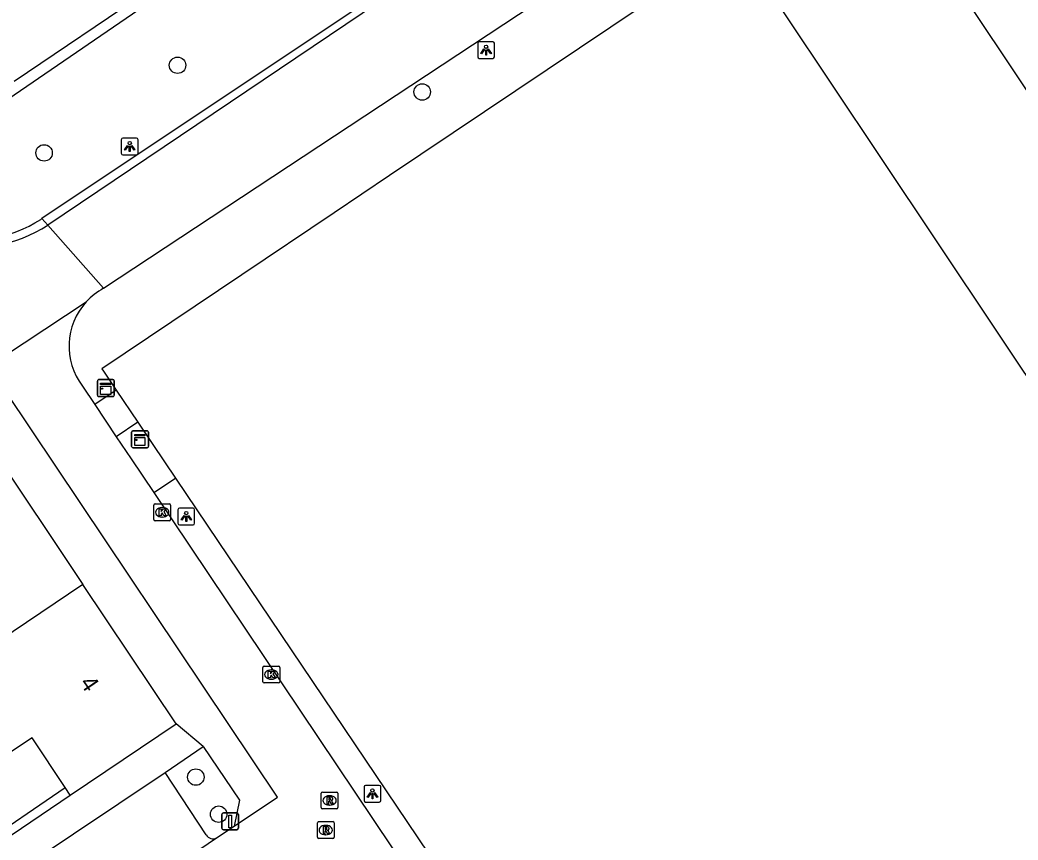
# Model space of a CAD drawing. Extents: x 158797 to 159887, y 384318 to 385255.
# Drawn here: x 159000.1 to 159059.5, y 384461 to 384509.8 of the extents above; entities that cross this region are included whole.
import ezdxf

# ---------------------------------------------------------------- set-up
doc = ezdxf.new("R2010")
doc.units = 0
for name, color, linetype in [('IMGEO_Boom', 7, 'Continuous'), ('IMGEO_Haag', 7, 'Continuous'), ('IMGEO_Kast', 7, 'Continuous'), ('IMGEO_Kolk', 7, 'Continuous'), ('IMGEO_Lichtpunt', 7, 'Continuous'), ('IMGEO_Pand', 7, 'Continuous'), ('IMGEO_Pand_nummerreeks', 7, 'Continuous'), ('IMGEO_Parkeervlak_open', 7, 'Continuous'), ('IMGEO_Rijbaan_lokaal_open', 7, 'Continuous'), ('IMGEO_Rioolput', 7, 'Continuous'), ('IMGEO_Verkeersbordpaal', 7, 'Continuous'), ('IMGEO_Voetpad_open', 7, 'Continuous')]:
    doc.layers.add(name, color=color, linetype=linetype)

msp = doc.modelspace()

# ---------------------------------------------------------------- linework, layer by layer
at = {"layer": 'IMGEO_Boom'}
for centre in [(159009.519, 384507.08), (159024.082, 384505.491), (159001.577, 384501.867), (159010.609, 384464.735), (159011.967, 384462.527)]:
    msp.add_circle(centre, 0.489, dxfattribs=at)
at = {"layer": 'IMGEO_Haag'}
for points in [[(158980.903, 384520.981), (158980.583, 384520.752), (158993.483, 384501.012), (159020.48, 384519.493)], [(159007.798, 384511.537), (158999.786, 384506.109)], [(158997.867, 384460.106), (158997.595, 384460.538), (159002.823, 384464.117)]]:
    msp.add_lwpolyline(points, dxfattribs=at)
at = {"layer": 'IMGEO_Kast'}
for p, q in [((159004.747, 384487.453), (159004.747, 384488.294)), ((159004.747, 384488.294), (159004.747, 384487.453)), ((159004.822, 384488.378), (159005.663, 384488.378)), ((159005.663, 384488.378), (159004.822, 384488.378)), ((159005.747, 384488.303), (159005.747, 384487.462)), ((159005.747, 384487.462), (159005.747, 384488.303)), ((159005.672, 384487.378), (159004.831, 384487.378)), ((159004.831, 384487.378), (159005.672, 384487.378)), ((159006.786, 384484.406), (159006.786, 384485.247)), ((159006.786, 384485.247), (159006.786, 384484.406)), ((159006.861, 384485.331), (159007.702, 384485.331)), ((159007.702, 384485.331), (159006.861, 384485.331)), ((159007.786, 384485.256), (159007.786, 384484.415)), ((159007.786, 384484.415), (159007.786, 384485.256)), ((159007.711, 384484.331), (159006.87, 384484.331)), ((159006.87, 384484.331), (159007.711, 384484.331))]:
    msp.add_line(p, q, dxfattribs=at)
for points in [[(159004.942, 384488.168), (159005.542, 384488.168), (159005.542, 384488.083), (159004.942, 384488.083), (159004.942, 384488.168)], [(159004.942, 384487.993), (159005.542, 384487.993), (159005.542, 384487.504), (159004.942, 384487.504), (159004.942, 384487.993)], [(159006.981, 384485.121), (159007.581, 384485.121), (159007.581, 384485.036), (159006.981, 384485.036), (159006.981, 384485.121)], [(159006.981, 384484.946), (159007.581, 384484.946), (159007.581, 384484.457), (159006.981, 384484.457), (159006.981, 384484.946)]]:
    msp.add_lwpolyline(points, dxfattribs=at)
for centre in [(159005.026, 384487.842), (159007.065, 384484.795)]:
    msp.add_circle(centre, 0.0377, dxfattribs=at)
for centre, start, end in [((159004.825, 384488.3), 92.4484, 184.28452), ((159004.825, 384488.3), 92.4484, 184.28452), ((159005.669, 384488.3), 2.4484, 94.28452), ((159005.669, 384488.3), 2.4484, 94.28452), ((159004.825, 384487.456), 182.4484, 274.28452), ((159004.825, 384487.456), 182.4484, 274.28452), ((159005.669, 384487.456), 272.4484, 4.28452), ((159005.669, 384487.456), 272.4484, 4.28452), ((159006.864, 384485.253), 92.4484, 184.28452), ((159006.864, 384485.253), 92.4484, 184.28452), ((159007.708, 384485.253), 2.4484, 94.28452), ((159007.708, 384485.253), 2.4484, 94.28452), ((159006.864, 384484.409), 182.4484, 274.28452), ((159006.864, 384484.409), 182.4484, 274.28452), ((159007.708, 384484.409), 272.4484, 4.28452), ((159007.708, 384484.409), 272.4484, 4.28452)]:
    msp.add_arc(centre, 0.0779, start, end, dxfattribs=at)
at = {"layer": 'IMGEO_Kolk'}
for p, q in [((159008.105, 384480.061), (159008.105, 384480.913)), ((159008.18, 384480.987), (159009.032, 384480.987)), ((159008.593, 384480.767), (159008.618, 384480.767)), ((159009.106, 384480.913), (159009.106, 384480.061)), ((159008.616, 384480.207), (159008.591, 384480.207)), ((159009.032, 384479.987), (159008.18, 384479.987)), ((159014.599, 384470.409), (159014.599, 384471.261)), ((159014.674, 384471.335), (159015.526, 384471.335)), ((159015.6, 384471.261), (159015.6, 384470.409)), ((159015.087, 384471.115), (159015.112, 384471.115)), ((159015.526, 384470.335), (159014.674, 384470.335)), ((159015.11, 384470.555), (159015.085, 384470.555))]:
    msp.add_line(p, q, dxfattribs=at)
for points in [[(159008.105, 384480.061), (159008.105, 384480.913)], [(159008.18, 384480.987), (159009.032, 384480.987)], [(159008.426, 384480.687), (159008.549, 384480.687), (159008.549, 384480.536), (159008.679, 384480.687), (159008.843, 384480.687), (159008.697, 384480.536), (159008.85, 384480.287), (159008.698, 384480.287), (159008.613, 384480.451), (159008.549, 384480.384), (159008.549, 384480.287), (159008.426, 384480.287), (159008.426, 384480.687)], [(159009.106, 384480.913), (159009.106, 384480.061)], [(159009.032, 384479.987), (159008.18, 384479.987)], [(159014.599, 384470.409), (159014.599, 384471.261)], [(159014.674, 384471.335), (159015.526, 384471.335)], [(159015.6, 384471.261), (159015.6, 384470.409)], [(159014.92, 384471.035), (159015.043, 384471.035), (159015.043, 384470.884), (159015.173, 384471.035), (159015.337, 384471.035), (159015.191, 384470.884), (159015.344, 384470.635), (159015.192, 384470.635), (159015.107, 384470.799), (159015.043, 384470.732), (159015.043, 384470.635), (159014.92, 384470.635), (159014.92, 384471.035)], [(159015.526, 384470.335), (159014.674, 384470.335)]]:
    msp.add_lwpolyline(points, dxfattribs=at)
for centre, start, end in [((159008.182, 384480.911), 91.55205, 178.44795), ((159008.182, 384480.911), 91.55205, 178.44795), ((159009.03, 384480.911), 1.55205, 88.44795), ((159009.03, 384480.911), 1.55205, 88.44795), ((159008.182, 384480.063), 181.55205, 268.44795), ((159008.182, 384480.063), 181.55205, 268.44795), ((159009.03, 384480.063), 271.55205, 358.44795), ((159009.03, 384480.063), 271.55205, 358.44795), ((159014.676, 384471.259), 91.55205, 178.44795), ((159014.676, 384471.259), 91.55205, 178.44795), ((159015.524, 384471.259), 1.55205, 88.44795), ((159015.524, 384471.259), 1.55205, 88.44795), ((159014.676, 384470.411), 181.55205, 268.44795), ((159014.676, 384470.411), 181.55205, 268.44795), ((159015.524, 384470.411), 271.55205, 358.44795), ((159015.524, 384470.411), 271.55205, 358.44795)]:
    msp.add_arc(centre, 0.0765, start, end, dxfattribs=at)
for centre, major_axis, ratio, start_param, end_param in [((159008.592, 384480.487), (-0.387, 0.002), 0.722429, 4.712389, 7.853982), ((159008.617, 384480.487), (-0.39, 0.002), 0.717154, 1.570796, 4.712389), ((159015.086, 384470.835), (-0.387, 0.002), 0.722429, 4.712389, 7.853982), ((159015.111, 384470.835), (-0.39, 0.002), 0.717154, 1.570796, 4.712389)]:
    msp.add_ellipse(centre, major_axis=major_axis, ratio=ratio, start_param=start_param, end_param=end_param, dxfattribs=at)
at = {"layer": 'IMGEO_Lichtpunt'}
for p, q in [((159027.385, 384508.388), (159027.385, 384507.581)), ((159027.385, 384508.388), (159027.385, 384507.581)), ((159028.287, 384508.483), (159027.479, 384508.483)), ((159028.287, 384508.483), (159027.479, 384508.483)), ((159028.381, 384507.581), (159028.381, 384508.388)), ((159028.381, 384507.581), (159028.381, 384508.388)), ((159027.479, 384507.487), (159028.287, 384507.487)), ((159027.479, 384507.487), (159028.287, 384507.487)), ((159006.173, 384502.649), (159006.173, 384501.842)), ((159006.173, 384502.649), (159006.173, 384501.842)), ((159007.075, 384502.744), (159006.267, 384502.744)), ((159007.075, 384502.744), (159006.267, 384502.744)), ((159007.169, 384501.842), (159007.169, 384502.649)), ((159007.169, 384501.842), (159007.169, 384502.649)), ((159006.267, 384501.748), (159007.075, 384501.748)), ((159006.267, 384501.748), (159007.075, 384501.748)), ((159010.443, 384480.734), (159009.635, 384480.734)), ((159010.443, 384480.734), (159009.635, 384480.734)), ((159009.541, 384480.639), (159009.541, 384479.832)), ((159009.541, 384480.639), (159009.541, 384479.832)), ((159010.537, 384479.832), (159010.537, 384480.639)), ((159010.537, 384479.832), (159010.537, 384480.639)), ((159009.635, 384479.738), (159010.443, 384479.738)), ((159009.635, 384479.738), (159010.443, 384479.738)), ((159020.621, 384464.148), (159020.621, 384463.341)), ((159020.621, 384464.148), (159020.621, 384463.341)), ((159021.523, 384464.243), (159020.715, 384464.243)), ((159021.523, 384464.243), (159020.715, 384464.243)), ((159021.617, 384463.341), (159021.617, 384464.148)), ((159021.617, 384463.341), (159021.617, 384464.148)), ((159020.715, 384463.247), (159021.523, 384463.247)), ((159020.715, 384463.247), (159021.523, 384463.247))]:
    msp.add_line(p, q, dxfattribs=at)
for points in [[(159027.759, 384508.052), (159027.798, 384508.024), (159027.61, 384507.762), (159027.572, 384507.789), (159027.759, 384508.052)], [(159027.861, 384508.004), (159027.908, 384508.004), (159027.908, 384507.682), (159027.861, 384507.682), (159027.861, 384508.004)], [(159027.971, 384508.024), (159028.009, 384508.051), (159028.196, 384507.789), (159028.157, 384507.761), (159027.971, 384508.024)], [(159006.547, 384502.313), (159006.586, 384502.285), (159006.398, 384502.023), (159006.36, 384502.05), (159006.547, 384502.313)], [(159006.649, 384502.265), (159006.696, 384502.265), (159006.696, 384501.943), (159006.649, 384501.943), (159006.649, 384502.265)], [(159006.759, 384502.285), (159006.797, 384502.312), (159006.984, 384502.05), (159006.945, 384502.022), (159006.759, 384502.285)], [(159009.915, 384480.303), (159009.954, 384480.275), (159009.766, 384480.013), (159009.728, 384480.04), (159009.915, 384480.303)], [(159010.017, 384480.255), (159010.064, 384480.255), (159010.064, 384479.933), (159010.017, 384479.933), (159010.017, 384480.255)], [(159010.127, 384480.275), (159010.165, 384480.302), (159010.352, 384480.04), (159010.313, 384480.012), (159010.127, 384480.275)], [(159020.995, 384463.812), (159021.034, 384463.784), (159020.846, 384463.522), (159020.808, 384463.549), (159020.995, 384463.812)], [(159021.097, 384463.764), (159021.144, 384463.764), (159021.144, 384463.442), (159021.097, 384463.442), (159021.097, 384463.764)], [(159021.207, 384463.784), (159021.245, 384463.811), (159021.432, 384463.549), (159021.393, 384463.521), (159021.207, 384463.784)]]:
    msp.add_lwpolyline(points, dxfattribs=at)
for centre in [(159027.884, 384508.186), (159006.672, 384502.447), (159010.04, 384480.437), (159021.12, 384463.946)]:
    msp.add_circle(centre, 0.0994, dxfattribs=at)
for centre, start, end in [((159027.479, 384508.388), 90, 180), ((159027.479, 384508.388), 90, 180), ((159028.287, 384508.388), 0, 90), ((159028.287, 384508.388), 0, 90), ((159027.479, 384507.581), 180, 270), ((159027.479, 384507.581), 180, 270), ((159028.287, 384507.581), 270, 0), ((159028.287, 384507.581), 270, 360), ((159006.267, 384502.649), 90, 180), ((159006.267, 384502.649), 90, 180), ((159007.075, 384502.649), 0, 90), ((159007.075, 384502.649), 0, 90), ((159006.267, 384501.842), 180, 270), ((159006.267, 384501.842), 180, 270), ((159007.075, 384501.842), 270, 0), ((159007.075, 384501.842), 270, 360), ((159009.635, 384480.639), 90, 180), ((159009.635, 384480.639), 90, 180), ((159010.443, 384480.639), 0, 90), ((159010.443, 384480.639), 0, 90), ((159009.635, 384479.832), 180, 270), ((159009.635, 384479.832), 180, 270), ((159010.443, 384479.832), 270, 0), ((159010.443, 384479.832), 270, 360), ((159020.715, 384464.148), 90, 180), ((159020.715, 384464.148), 90, 180), ((159021.523, 384464.148), 0, 90), ((159021.523, 384464.148), 0, 90), ((159020.715, 384463.341), 180, 270), ((159020.715, 384463.341), 180, 270), ((159021.523, 384463.341), 270, 0), ((159021.523, 384463.341), 270, 360)]:
    msp.add_arc(centre, 0.0946, start, end, dxfattribs=at)
at = {"layer": 'IMGEO_Pand'}
for points in [[(159050.67, 384519.624), (159058.757, 384507.518), (159100.592, 384444.894), (159099.734, 384444.322), (159105.622, 384435.536)], [(159042.827, 384514.395), (159022.135, 384500.517), (159018.834, 384498.302), (159013.348, 384494.623), (159005.008, 384489.029), (159005.108, 384488.881), (159005.874, 384487.744)], [(159099.728, 384431.577), (159096.595, 384436.272), (159093.851, 384440.4), (159092.757, 384439.671), (159051.335, 384501.662), (159042.827, 384514.395)], [(159005.874, 384487.744), (159007.154, 384485.844)], [(159007.154, 384485.844), (159008.052, 384484.512), (159009.399, 384482.514)], [(158992.412, 384480.438), (158998.364, 384484.427), (159003.891, 384476.185)], [(159009.399, 384482.514), (159030.087, 384451.818), (159051.932, 384419.406)], [(159003.891, 384476.185), (158996.366, 384471.143)], [(159009.443, 384467.906), (159003.891, 384476.185)], [(159002.823, 384464.117), (159000.858, 384467.062), (158999.645, 384466.25), (158996.366, 384471.143)], [(159003.132, 384463.653), (159009.443, 384467.906)], [(159003.132, 384463.653), (159002.823, 384464.117)]]:
    msp.add_lwpolyline(points, dxfattribs=at)
at = {"layer": 'IMGEO_Parkeervlak_open'}
msp.add_lwpolyline([(159011.225, 384461.303), (159008.779, 384465.005)], dxfattribs=at)
msp.add_arc((159011.621, 384461.511), 0.447, 207.67617, 300.16513, dxfattribs=at)
at = {"layer": 'IMGEO_Rijbaan_lokaal_open'}
for points in [[(159005.109, 384493.811), (159040.833, 384517.38), (159048.701, 384522.571), (159071.071, 384537.329)], [(159027.435, 384514.841), (159001.809, 384497.57)], [(159025.503, 384514.018), (159001.451, 384497.958)], [(159001.451, 384497.958), (159001.376, 384497.908)], [(159001.451, 384497.958), (159001.809, 384497.57)], [(159005.109, 384493.811), (159001.809, 384497.57)], [(158997.914, 384488.95), (159004.079, 384493.004)], [(159003.855, 384487.994), (159004.594, 384486.892)], [(159012.899, 384461.808), (159015.46, 384463.54), (158999.348, 384487.608)], [(159004.594, 384486.892), (159005.876, 384484.983)], [(159005.876, 384484.983), (159006.753, 384483.677), (159008.108, 384481.658)], [(159008.108, 384481.658), (159049.456, 384420.063)], [(159011.846, 384461.124), (159012.899, 384461.808)], [(159002.994, 384455.113), (159011.846, 384461.124)]]:
    msp.add_lwpolyline(points, dxfattribs=at)
for centre, radius, start, end in [((158997.197, 384504.786), 8.564, 211.85792, 302.58272), ((158997.097, 384504.614), 7.955, 211.32733, 302.5414), ((159006.968, 384490.378), 3.904, 118.43115, 137.7259), ((159006.976, 384490.364), 3.919, 137.66268, 217.21728)]:
    msp.add_arc(centre, radius, start, end, dxfattribs=at)
at = {"layer": 'IMGEO_Rioolput'}
for p, q in [((159018.067, 384462.92), (159018.067, 384463.772)), ((159018.142, 384463.846), (159018.994, 384463.846)), ((159018.555, 384463.626), (159018.58, 384463.626)), ((159019.068, 384463.772), (159019.068, 384462.92)), ((159018.994, 384462.846), (159018.142, 384462.846)), ((159018.578, 384463.066), (159018.553, 384463.066)), ((159017.842, 384461.159), (159017.842, 384462.011)), ((159017.917, 384462.085), (159018.769, 384462.085)), ((159018.33, 384461.865), (159018.355, 384461.865)), ((159018.843, 384462.011), (159018.843, 384461.159)), ((159018.769, 384461.085), (159017.917, 384461.085)), ((159018.353, 384461.305), (159018.328, 384461.305))]:
    msp.add_line(p, q, dxfattribs=at)
for points in [[(159018.067, 384462.92), (159018.067, 384463.772)], [(159018.142, 384463.846), (159018.994, 384463.846)], [(159018.656, 384463.544), (159018.404, 384463.546), (159018.404, 384463.146)], [(159018.582, 384463.465), (159018.528, 384463.465), (159018.528, 384463.384)], [(159019.068, 384463.772), (159019.068, 384462.92)], [(159018.994, 384462.846), (159018.142, 384462.846)], [(159018.404, 384463.146), (159018.528, 384463.146), (159018.528, 384463.308), (159018.539, 384463.308)], [(159018.528, 384463.384), (159018.58, 384463.384)], [(159018.586, 384463.279), (159018.657, 384463.146), (159018.797, 384463.146), (159018.732, 384463.272)], [(159017.842, 384461.159), (159017.842, 384462.011)], [(159017.917, 384462.085), (159018.769, 384462.085)], [(159018.431, 384461.783), (159018.179, 384461.785), (159018.179, 384461.385)], [(159018.357, 384461.704), (159018.303, 384461.704), (159018.303, 384461.623)], [(159018.843, 384462.011), (159018.843, 384461.159)], [(159018.769, 384461.085), (159017.917, 384461.085)], [(159018.179, 384461.385), (159018.303, 384461.385), (159018.303, 384461.547), (159018.314, 384461.547)], [(159018.303, 384461.623), (159018.355, 384461.623)], [(159018.361, 384461.518), (159018.432, 384461.385), (159018.572, 384461.385), (159018.507, 384461.511)]]:
    msp.add_lwpolyline(points, dxfattribs=at)
for centre, radius, start, end in [((159018.144, 384463.77), 0.0765, 91.55205, 178.44795), ((159018.144, 384463.77), 0.0765, 91.55205, 178.44795), ((159018.588, 384463.369), 0.0964, 77.00612, 93.18647), ((159018.602, 384463.426), 0.0378, 276.66336, 79.67722), ((159018.655, 384463.434), 0.109, 350.36119, 89.41601), ((159018.992, 384463.77), 0.0765, 1.55205, 88.44795), ((159018.992, 384463.77), 0.0765, 1.55205, 88.44795), ((159018.144, 384462.922), 0.0765, 181.55205, 268.44795), ((159018.144, 384462.922), 0.0765, 181.55205, 268.44795), ((159018.538, 384463.255), 0.0533, 26.02933, 88.69889), ((159018.564, 384463.573), 0.19, 274.7715, 282.96867), ((159018.653, 384463.434), 0.112, 277.58423, 350.98172), ((159018.637, 384463.219), 0.108, 29.51342, 73.79051), ((159018.992, 384462.922), 0.0765, 271.55205, 358.44795), ((159018.992, 384462.922), 0.0765, 271.55205, 358.44795), ((159017.919, 384462.009), 0.0765, 91.55205, 178.44795), ((159017.919, 384462.009), 0.0765, 91.55205, 178.44795), ((159018.363, 384461.608), 0.0964, 77.00612, 93.18647), ((159018.377, 384461.665), 0.0378, 276.66336, 79.67722), ((159018.43, 384461.673), 0.109, 350.36119, 89.41601), ((159018.428, 384461.673), 0.112, 277.58423, 350.98172), ((159018.767, 384462.009), 0.0765, 1.55205, 88.44795), ((159018.767, 384462.009), 0.0765, 1.55205, 88.44795), ((159017.919, 384461.161), 0.0765, 181.55205, 268.44795), ((159017.919, 384461.161), 0.0765, 181.55205, 268.44795), ((159018.313, 384461.494), 0.0533, 26.02933, 88.69889), ((159018.339, 384461.812), 0.19, 274.7715, 282.96867), ((159018.412, 384461.458), 0.108, 29.51342, 73.79051), ((159018.767, 384461.161), 0.0765, 271.55205, 358.44795), ((159018.767, 384461.161), 0.0765, 271.55205, 358.44795)]:
    msp.add_arc(centre, radius, start, end, dxfattribs=at)
for centre, major_axis, ratio, start_param, end_param in [((159018.554, 384463.346), (-0.387, 0.002), 0.722429, 4.712389, 7.853982), ((159018.579, 384463.346), (-0.39, 0.002), 0.717154, 1.570796, 4.712389), ((159018.329, 384461.585), (-0.387, 0.002), 0.722429, 4.712389, 7.853982), ((159018.354, 384461.585), (-0.39, 0.002), 0.717154, 1.570796, 4.712389)]:
    msp.add_ellipse(centre, major_axis=major_axis, ratio=ratio, start_param=start_param, end_param=end_param, dxfattribs=at)
at = {"layer": 'IMGEO_Verkeersbordpaal'}
for p, q in [((159012.156, 384461.701), (159012.156, 384462.501)), ((159012.156, 384462.501), (159012.156, 384461.701)), ((159012.256, 384462.601), (159013.046, 384462.601)), ((159013.046, 384462.601), (159012.256, 384462.601)), ((159013.146, 384462.501), (159013.146, 384461.701)), ((159013.146, 384461.701), (159013.146, 384462.501)), ((159013.046, 384461.601), (159012.256, 384461.601)), ((159012.256, 384461.601), (159013.046, 384461.601))]:
    msp.add_line(p, q, dxfattribs=at)
msp.add_lwpolyline([(159012.576, 384462.476), (159012.726, 384462.476), (159012.726, 384461.726), (159012.576, 384461.726), (159012.576, 384462.476)], dxfattribs=at)
for centre, start, end in [((159012.256, 384462.501), 90, 180), ((159012.256, 384462.501), 90, 180), ((159013.046, 384462.501), 0, 90), ((159013.046, 384462.501), 360, 90), ((159012.256, 384461.701), 180, 270), ((159012.256, 384461.701), 180, 270), ((159013.046, 384461.701), 270, 0), ((159013.046, 384461.701), 270, 0)]:
    msp.add_arc(centre, 0.1, start, end, dxfattribs=at)
at = {"layer": 'IMGEO_Voetpad_open'}
for points in [[(159005.874, 384487.744), (159004.594, 384486.892)], [(159007.154, 384485.844), (159005.876, 384484.983)], [(159008.108, 384481.658), (159009.399, 384482.514)], [(159011.053, 384466.564), (159009.443, 384467.906)], [(159008.779, 384465.005), (159011.053, 384466.564)], [(159011.053, 384466.564), (159013.217, 384463.362), (159012.899, 384461.808)], [(159000.565, 384459.513), (159008.779, 384465.005)], [(158997.867, 384460.106), (159003.132, 384463.653)]]:
    msp.add_lwpolyline(points, dxfattribs=at)

# ---------------------------------------------------------------- texts
at = {"layer": 'IMGEO_Pand_nummerreeks'}
msp.add_text('4', height=1, rotation=304.17099, dxfattribs=at).set_placement((159003.671, 384470.337))

doc.saveas('drawing.dxf')
